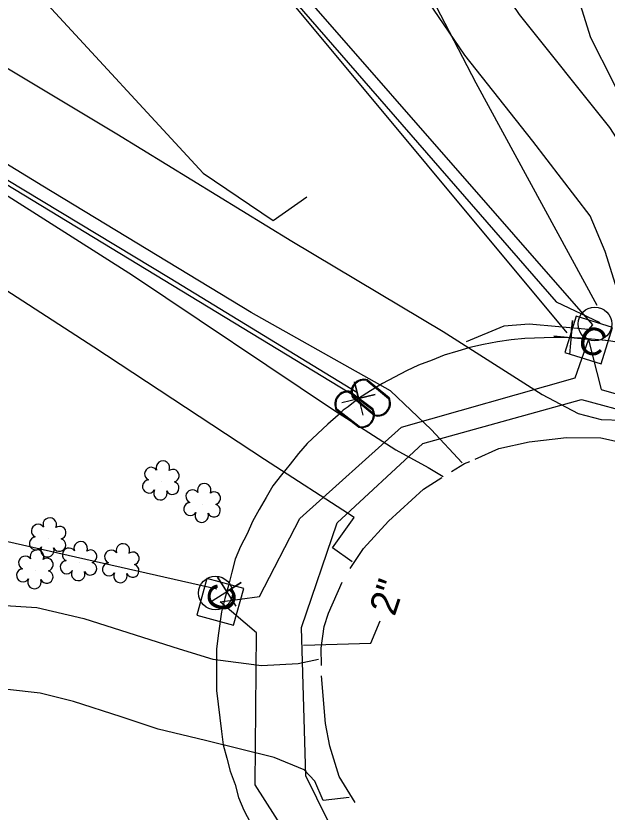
# Model space of a CAD drawing. Extents: x 3040896 to 3051146, y 687568 to 732976.
# Drawn here: x 3049293.4 to 3049379.7, y 694095.5 to 694211.6 of the extents above; entities that cross this region are included whole.
import ezdxf

# ---------------------------------------------------------------- set-up
doc = ezdxf.new("R2010")
doc.units = 0
for name, color, linetype in [('Exist Other Culture Fence Line', 7, 'Continuous'), ('Exist Property Corner CELL', 7, 'Continuous'), ('Exist Property Line', 7, 'Continuous'), ('Exist Roads Change in Surface', 7, 'Continuous'), ('Exist Roads EOP', 7, 'Continuous'), ('Exist Roads EOP Other', 7, 'Continuous'), ('Exist Utilities Other Pole CELL', 7, 'Continuous'), ('Exist Utilities Power UG Cable', 7, 'Continuous'), ('Exist Utilities Power UG Cable SUE', 7, 'Continuous'), ('Exist Utilities TV Pedestal CELL', 7, 'Continuous'), ('Exist Utilities TV UG Cable', 7, 'Continuous'), ('Exist Utilities Water Meter CELL', 7, 'Continuous'), ('Exist Utilities Water UG Line', 7, 'Continuous'), ('Exist Utilities Water UG Line Leader', 7, 'Continuous'), ('Exist Utilities Water UG Line Text', 7, 'Continuous'), ('Exist Vegetation Shrub CELL', 7, 'Continuous'), ('Exist Vegetation Woods Line', 7, 'Continuous'), ('Old_Level_13', 7, 'Continuous')]:
    doc.layers.add(name, color=color, linetype=linetype)

msp = doc.modelspace()

# ---------------------------------------------------------------- linework, layer by layer
at = {"layer": 'Exist Other Culture Fence Line'}
for points in [[(3049330.38, 694220.57), (3049366.06, 694179.77), (3049377.57, 694166.56), (3049377, 694165.91), (3049368.32, 694166.67), (3049364.64, 694166.36), (3049359.13, 694164.11)], [(3049296.88, 694214.63), (3049320.78, 694188.72), (3049330.98, 694181.79), (3049335.89, 694185.24)], [(3049254.67, 694210.36), (3049315.95, 694173.39), (3049343.21, 694156.73)]]:
    msp.add_lwpolyline(points, dxfattribs=at)
at = {"layer": 'Exist Property Corner CELL'}
for p, q in [((3049374.43, 694164.72), (3049374.43, 694164.72)), ((3049343.45, 694155.82), (3049343.45, 694155.82)), ((3049324.21, 694127.65), (3049324.21, 694127.65))]:
    msp.add_line(p, q, dxfattribs=at)
for points in [[(3049371.94, 694164.95), (3049376.92, 694164.5), (3049374.43, 694164.72), (3049374.66, 694167.21), (3049374.21, 694162.23)], [(3049341.02, 694155.22), (3049345.88, 694156.41), (3049343.45, 694155.82), (3049342.86, 694158.25), (3049344.05, 694153.39)], [(3049322.1, 694126.32), (3049326.33, 694128.98), (3049324.21, 694127.65), (3049322.88, 694129.77), (3049325.55, 694125.54)]]:
    msp.add_lwpolyline(points, dxfattribs=at)
at = {"layer": 'Exist Property Line'}
for p, q in [((3049373.88, 694165.39), (3049211.06, 694360.91)), ((3049343.21, 694155.97), (3049103.55, 694301.39)), ((3049322.74, 694127.99), (3049093.43, 694180.09))]:
    msp.add_line(p, q, dxfattribs=at)
at = {"layer": 'Exist Roads Change in Surface'}
for points in [[(3049360.44, 694147), (3049363.91, 694148.52), (3049368.36, 694149.51), (3049373.78, 694150.15), (3049378.82, 694150.1), (3049384.11, 694148.91), (3049389.7, 694145.78), (3049395.26, 694142.23), (3049399.41, 694137.41)], [(3049342.2, 694131.01), (3049344.16, 694133.95), (3049347.8, 694137.93), (3049352.93, 694142.59), (3049355.62, 694144.31)], [(3049342.94, 694096.9), (3049340.62, 694100.68), (3049339.27, 694105.09), (3049338.6, 694108.43), (3049338.05, 694115.36)]]:
    msp.add_lwpolyline(points, dxfattribs=at)
at = {"layer": 'Exist Roads EOP'}
for points in [[(3049356.99, 694145.16), (3049358.9, 694146.33), (3049359.66, 694146.66)], [(3049338.02, 694116.87), (3049337.98, 694119.43), (3049338.45, 694122.59), (3049339.07, 694124.52), (3049341.07, 694129.03)]]:
    msp.add_lwpolyline(points, dxfattribs=at)
at = {"layer": 'Exist Roads EOP Other'}
for points in [[(3049354.48, 694231.1), (3049358.82, 694223.83), (3049366.88, 694211.85), (3049380.05, 694195.38), (3049387.01, 694184.59), (3049389.74, 694178.58), (3049391.78, 694171.41), (3049393.22, 694159.14), (3049394.93, 694146.29), (3049399.92, 694143.12), (3049399.29, 694137.56)], [(3049277, 694213.12), (3049308.19, 694194.43), (3049333.7, 694178.77), (3049355.79, 694165.62), (3049370.24, 694156.42), (3049375.49, 694153.65), (3049378.85, 694152.77), (3049381.93, 694152.68), (3049382.21, 694154.01), (3049382.52, 694158.99), (3049382.08, 694166.09), (3049381.2, 694171.7), (3049379.44, 694177.25), (3049377.24, 694182.46), (3049368.89, 694193.39), (3049358.95, 694205.89), (3049351.35, 694217.12), (3049345.55, 694226.27)], [(3049358.57, 694146.42), (3049354.06, 694151.29), (3049348.12, 694156.95), (3049327.76, 694168.36), (3049297.38, 694186.82), (3049256.01, 694212.1)], [(3049253.98, 694209.66), (3049310.44, 694173.82), (3049339.78, 694154.18), (3049348.9, 694148.33), (3049353.59, 694145.76), (3049355.77, 694144.47)], [(3049342.5, 694131.99), (3049339.66, 694134.03), (3049342.79, 694138.48), (3049329.71, 694146.94), (3049304.82, 694163.34), (3049279.76, 694179.52), (3049245.65, 694200.48), (3049234.68, 694206.55)], [(3049174.34, 694144.8), (3049178.82, 694145.69), (3049186.35, 694146.03), (3049191.99, 694146.39), (3049197.6, 694145.44), (3049204.1, 694142.96), (3049211.65, 694138.2), (3049218.01, 694134.51), (3049224.18, 694131.93), (3049229.11, 694130.91), (3049238.94, 694129.45), (3049258.28, 694127.6), (3049274.1, 694126.77), (3049296.5, 694125.32), (3049303.37, 694123.71), (3049317.28, 694119.3), (3049322.18, 694117.8), (3049329.27, 694116.87), (3049334.62, 694117.19), (3049337.61, 694117.79)], [(3049342.09, 694097.6), (3049338.26, 694097.18), (3049337.05, 694099.98), (3049335.52, 694101.66), (3049331.11, 694103.46), (3049321.13, 694105.93), (3049314.18, 694107.59), (3049308.8, 694109.37), (3049301.85, 694111.62), (3049297, 694112.86), (3049287.86, 694113.85), (3049261.53, 694115.8), (3049241.79, 694117.24), (3049222.7, 694117.9), (3049214.6, 694117.33), (3049184.74, 694112.26), (3049180.39, 694111.4)]]:
    msp.add_lwpolyline(points, dxfattribs=at)
at = {"layer": 'Exist Utilities Other Pole CELL'}
for centre in [(3049377.93, 694166.7), (3049322.57, 694127.45)]:
    msp.add_circle(centre, 2.46, dxfattribs=at)
at = {"layer": 'Exist Utilities Power UG Cable'}
msp.add_lwpolyline([(3049272.38, 694284.71), (3049372.26, 694169.93), (3049378.67, 694166.89)], dxfattribs=at)
at = {"layer": 'Exist Utilities Power UG Cable SUE'}
msp.add_lwpolyline([(3049322.52, 694289.42), (3049332.8, 694255.39), (3049360.55, 694201.88), (3049378.23, 694169.46)], dxfattribs=at)
at = {"layer": 'Exist Utilities TV Pedestal CELL'}
for p, q in [((3049377.01, 694164.37), (3049377.01, 694164.37)), ((3049323.27, 694126.17), (3049323.27, 694126.17))]:
    msp.add_line(p, q, dxfattribs=at)
for points in [[(3049373.54, 694162.55), (3049378.84, 694160.9), (3049380.49, 694166.2), (3049375.19, 694167.85), (3049373.54, 694162.55)], [(3049325.21, 694122.76), (3049326.68, 694128.11), (3049321.32, 694129.58), (3049319.86, 694124.22), (3049325.21, 694122.76)]]:
    msp.add_lwpolyline(points, dxfattribs=at)
at = {"layer": 'Exist Utilities TV UG Cable'}
msp.add_lwpolyline([(3049338.91, 694082.96), (3049328.34, 694099.45), (3049328.55, 694121.64), (3049323.27, 694126.17), (3049328.98, 694126.92), (3049334.89, 694138.34), (3049349.69, 694151.66), (3049375.06, 694158.84), (3049377.01, 694164.37), (3049378.86, 694157.15), (3049391.33, 694153.56), (3049402.11, 694147.85), (3049406.76, 694142.99), (3049416.91, 694128.19), (3049427.9, 694120.16), (3049446.71, 694116.57), (3049485.61, 694119.53)], dxfattribs=at)
at = {"layer": 'Exist Utilities Water Meter CELL'}
for p, q in [((3049345.24, 694155.95), (3049345.24, 694155.95)), ((3049342.88, 694154.24), (3049342.88, 694154.24))]:
    msp.add_line(p, q, dxfattribs=at)
for points in [[(3049344.67, 694158.46), (3049347.81, 694155.85)], [(3049344.76, 694158.56), (3049347.89, 694155.96)], [(3049342.21, 694156.71), (3049345.44, 694154.24)], [(3049342.29, 694156.82), (3049345.53, 694154.35)], [(3049345.72, 694153.34), (3049342.57, 694155.96)], [(3049345.81, 694153.45), (3049342.66, 694156.07)], [(3049343.46, 694151.65), (3049340.21, 694154.14)], [(3049343.55, 694151.76), (3049340.29, 694154.25)]]:
    msp.add_lwpolyline(points, dxfattribs=at)
for centre, radius, start, end in [((3049344.23, 694156.78), 1.86, 73.479, 206.2803), ((3049344.24, 694156.78), 1.73, 75.6019, 204.0833), ((3049341.83, 694155.03), 1.86, 75.7966, 208.5979), ((3049341.84, 694155.02), 1.73, 77.9195, 206.4009), ((3049346.24, 694155.13), 1.86, 253.9492, 26.6093), ((3049346.24, 694155.12), 1.73, 255.4281, 25.1738), ((3049343.9, 694153.45), 1.86, 256.2669, 28.9269), ((3049343.91, 694153.44), 1.73, 257.7457, 27.4914)]:
    msp.add_arc(centre, radius, start, end, dxfattribs=at)
at = {"layer": 'Exist Utilities Water UG Line'}
msp.add_lwpolyline([(3049342.2, 694087.66), (3049335.74, 694100.79), (3049335.13, 694122.44), (3049340.31, 694137.69), (3049352.81, 694149.27), (3049375.99, 694155.68), (3049391.84, 694151.41), (3049403.12, 694141.95), (3049414.71, 694126.1), (3049425.69, 694116.95), (3049446.36, 694112.97), (3049467.4, 694111.82), (3049483.67, 694114.36), (3049499.11, 694119.85)], dxfattribs=at)
at = {"layer": 'Exist Utilities Water UG Line Leader'}
msp.add_lwpolyline([(3049335.41, 694119.82), (3049345.24, 694120.14), (3049346.62, 694123.39)], dxfattribs=at)
at = {"layer": 'Exist Vegetation Shrub CELL'}
for p, q in [((3049314.66, 694143.69), (3049314.66, 694143.69)), ((3049320.69, 694140.41), (3049320.69, 694140.41)), ((3049298.16, 694135.39), (3049298.16, 694135.39)), ((3049302.67, 694131.93), (3049302.67, 694131.93)), ((3049296.29, 694130.73), (3049296.29, 694130.73)), ((3049308.83, 694131.62), (3049308.83, 694131.62))]:
    msp.add_line(p, q, dxfattribs=at)
for centre, radius, start, end in [((3049313.18, 694144.82), 0.968, 35.8908, 245.4216), ((3049314.89, 694145.74), 0.99, 334.8391, 200.4717), ((3049316.34, 694144.56), 0.929, 284.4567, 126.0861), ((3049312.86, 694142.99), 0.955, 95.1099, 327.9534), ((3049316.3, 694142.77), 0.937, 204.9913, 73.4601), ((3049320.92, 694142.45), 0.99, 334.8391, 200.4717), ((3049314.54, 694142.01), 0.984, 151.2797, 21.387), ((3049319.21, 694141.54), 0.968, 35.8908, 245.4216), ((3049322.37, 694141.28), 0.929, 284.4567, 126.0861), ((3049318.89, 694139.71), 0.955, 95.1099, 327.9534), ((3049322.33, 694139.49), 0.937, 204.9913, 73.4601), ((3049320.56, 694138.73), 0.984, 151.2797, 21.387), ((3049298.39, 694137.43), 0.99, 334.8391, 200.4717), ((3049296.67, 694136.51), 0.968, 35.8908, 245.4216), ((3049299.83, 694136.25), 0.929, 284.4567, 126.0861), ((3049296.36, 694134.68), 0.955, 95.1099, 327.9534), ((3049299.79, 694134.46), 0.937, 204.9913, 73.4601), ((3049298.03, 694133.7), 0.984, 151.2797, 21.387), ((3049302.9, 694133.97), 0.99, 334.8391, 200.4717), ((3049309.06, 694133.66), 0.99, 334.8391, 200.4717), ((3049296.52, 694132.77), 0.99, 334.8391, 200.4717), ((3049301.19, 694133.05), 0.968, 35.8908, 245.4216), ((3049304.34, 694132.8), 0.929, 284.4567, 126.0861), ((3049307.35, 694132.74), 0.968, 35.8908, 245.4216), ((3049310.51, 694132.49), 0.929, 284.4567, 126.0861), ((3049294.81, 694131.86), 0.968, 35.8908, 245.4216), ((3049297.96, 694131.6), 0.929, 284.4567, 126.0861), ((3049300.87, 694131.22), 0.955, 95.1099, 327.9534), ((3049304.31, 694131), 0.937, 204.9913, 73.4601), ((3049307.03, 694130.91), 0.955, 95.1099, 327.9534), ((3049294.49, 694130.03), 0.955, 95.1099, 327.9534), ((3049297.93, 694129.8), 0.937, 204.9913, 73.4601), ((3049302.54, 694130.24), 0.984, 151.2797, 21.387), ((3049310.47, 694130.69), 0.937, 204.9913, 73.4601), ((3049296.16, 694129.05), 0.984, 151.2797, 21.387), ((3049308.7, 694129.93), 0.984, 151.2797, 21.387)]:
    msp.add_arc(centre, radius, start, end, dxfattribs=at)
at = {"layer": 'Exist Vegetation Woods Line'}
msp.add_lwpolyline([(3049374.37, 694216.3), (3049379.21, 694217.26), (3049382.81, 694217.9), (3049386.88, 694215.73), (3049390.14, 694213.1), (3049392.37, 694209.01), (3049394.89, 694204.7), (3049396.28, 694200.04), (3049397.14, 694195.65), (3049396.99, 694192.07), (3049393.79, 694189.74), (3049389.83, 694189.11), (3049386.36, 694191.63), (3049383.63, 694195.61), (3049380.6, 694202.01), (3049377.34, 694208.45), (3049375.61, 694214.07), (3049374.37, 694216.3)], dxfattribs=at)
at = {"layer": 'Old_Level_13'}
for points in [[(3049371.95, 694164.75), (3049367.7, 694164.57), (3049365.7, 694164.38), (3049363.7, 694164.07), (3049361.7, 694163.69), (3049359.7, 694163.25), (3049357.95, 694162.75), (3049355.95, 694162.13), (3049354.2, 694161.44), (3049352.2, 694160.69), (3049350.45, 694159.88), (3049348.7, 694158.94), (3049346.95, 694158), (3049345.2, 694156.94), (3049343.45, 694155.82), (3049341.95, 694154.63), (3049341.2, 694154.13)], [(3049371.95, 694164.75), (3049367.7, 694164.57), (3049365.7, 694164.38), (3049363.7, 694164.07), (3049361.7, 694163.69), (3049359.7, 694163.25), (3049357.95, 694162.75), (3049355.95, 694162.13), (3049354.2, 694161.44), (3049352.2, 694160.69), (3049350.45, 694159.88), (3049348.7, 694158.94), (3049346.95, 694158), (3049345.2, 694156.94), (3049343.45, 694155.82), (3049341.95, 694154.63), (3049341.2, 694154.13)], [(3049404.2, 694154.32), (3049401.95, 694155.38), (3049400.45, 694156.5), (3049398.7, 694157.57), (3049396.95, 694158.57), (3049395.2, 694159.5), (3049393.2, 694160.32), (3049391.45, 694161.13), (3049389.7, 694161.82), (3049387.7, 694162.44), (3049385.7, 694163), (3049383.95, 694163.5), (3049381.95, 694163.88), (3049379.95, 694164.25), (3049377.95, 694164.44), (3049375.95, 694164.63), (3049373.95, 694164.75), (3049371.95, 694164.75)], [(3049404.2, 694154.32), (3049401.95, 694155.38), (3049400.45, 694156.5), (3049398.7, 694157.57), (3049396.95, 694158.57), (3049395.2, 694159.5), (3049393.2, 694160.32), (3049391.45, 694161.13), (3049389.7, 694161.82), (3049387.7, 694162.44), (3049385.7, 694163), (3049383.95, 694163.5), (3049381.95, 694163.88), (3049379.95, 694164.25), (3049377.95, 694164.44), (3049375.95, 694164.63), (3049373.95, 694164.75), (3049371.95, 694164.75)], [(3049341.2, 694154.13), (3049340.45, 694153.38), (3049338.95, 694152.07), (3049337.45, 694150.69), (3049335.95, 694149.25), (3049334.7, 694147.82), (3049333.45, 694146.25), (3049332.2, 694144.69), (3049330.95, 694143.07), (3049329.95, 694141.38), (3049328.95, 694139.63), (3049327.95, 694137.88), (3049327.2, 694136.07), (3049326.2, 694134.25), (3049325.45, 694132.38), (3049324.95, 694130.5), (3049324.45, 694128.57), (3049323.95, 694126.63), (3049323.45, 694124.69)], [(3049341.2, 694154.13), (3049340.45, 694153.38), (3049338.95, 694152.07), (3049337.45, 694150.69), (3049335.95, 694149.25), (3049334.7, 694147.82), (3049333.45, 694146.25), (3049332.2, 694144.69), (3049330.95, 694143.07), (3049329.95, 694141.38), (3049328.95, 694139.63), (3049327.95, 694137.88), (3049327.2, 694136.07), (3049326.2, 694134.25), (3049325.45, 694132.38), (3049324.95, 694130.5), (3049324.45, 694128.57), (3049323.95, 694126.63), (3049323.45, 694124.69)], [(3049323.45, 694124.69), (3049322.95, 694121.25), (3049322.7, 694119.25), (3049322.7, 694117.25), (3049322.7, 694115.25), (3049322.7, 694113.25), (3049322.95, 694111.25), (3049323.2, 694109.25), (3049323.45, 694107.25), (3049323.7, 694105.32), (3049324.2, 694103.38), (3049324.7, 694101.44), (3049325.45, 694099.5), (3049325.95, 694097.63), (3049326.7, 694095.75), (3049327.7, 694093.94)], [(3049323.45, 694124.69), (3049322.95, 694121.25), (3049322.7, 694119.25), (3049322.7, 694117.25), (3049322.7, 694115.25), (3049322.7, 694113.25), (3049322.95, 694111.25), (3049323.2, 694109.25), (3049323.45, 694107.25), (3049323.7, 694105.32), (3049324.2, 694103.38), (3049324.7, 694101.44), (3049325.45, 694099.5), (3049325.95, 694097.63), (3049326.7, 694095.75), (3049327.7, 694093.94)]]:
    msp.add_lwpolyline(points, dxfattribs=at)

# ---------------------------------------------------------------- texts
at = {"layer": 'Exist Utilities TV Pedestal CELL'}
for rotation, p in [(342.7283, (3049375.17, 694162.85)), (74.6667, (3049324.85, 694124.38))]:
    msp.add_text('C', height=4, rotation=rotation, dxfattribs=at).set_placement(p)
at = {"layer": 'Exist Utilities Water UG Line Text'}
msp.add_text('2"', height=4, rotation=71.222, dxfattribs=at).set_placement((3049348.69, 694123.94))

doc.saveas('drawing.dxf')
